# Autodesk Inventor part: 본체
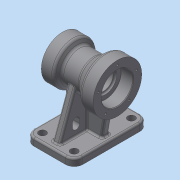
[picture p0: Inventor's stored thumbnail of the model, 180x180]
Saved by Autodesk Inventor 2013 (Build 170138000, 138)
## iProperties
Created: 2015-08
Part Number: 본체
Material: 일반
Document SubType Name: Modeling
Designer: Administrator
Density: 1 g/cm^3
Author: Administrator
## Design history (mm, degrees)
sketch "스케치1"
  geometry: L1 (0, 0)-(90, 0); L2 (0, 0)-(0, 35); L3 (0, 35)-(20, 35); L4 (20, 35)-(25.196, 26); L5 (25.196, 26)-(53.315, 26); L6 (53.315, 26)-(70, 40); L7 (70, 40)-(90, 40); L8 (90, 40)-(90, 0)
  constraints: 16 end point, 3 parallel, 2 perpendicular, 1 horizontal
  dimensions: "d0" = 90 distance of L1.start L1.end; "d1" = 70 diameter of L3 L1; "d2" = 20 distance of L2.end L3.end; "d3" = 60 deg angle of L5 L4; "d4" = 20 distance of L6.end L7.end; "d5" = 80 diameter of L7 L1; "d6" = 40 deg angle of L5 L6; "d7" = 52 diameter of L5 L1
revolve "회전1" sketch "스케치1" stored, may be unused: angle "d8" = 90 deg
sketch "스케치2"
  geometry: L1 (-61, -78)-(61, -78); L2 (61, -78)-(61, -90); L3 (61, -90)-(-61, -90); L4 (-61, -90)-(-61, -78); 2 further points
  constraints: 8 end point, 2 parallel, 1 horizontal, 1 midpoint, 1 perpendicular, 1 vertical alignment
  dimensions: "d9" = 90 distance from line of L3 point (0, 0); "d10" = 12 distance of L3.end L1.start; "d11" = 122 distance of L2.end L3.end
extrude "돌출1" join sketch "스케치2" distance "d12" = 80; taper "d13" = 0 deg
node "작업 평면1"
sketch "스케치3"
  geometry: L1 (-6, 0)-(6, 0); L2 (6, 0)-(6, -78); L3 (6, -78)-(-6, -78); L4 (-6, -78)-(-6, 0); L5 (-61, -90)-(-61, -78) reference; L6 (-61, -78)-(61, -78) reference; L7 (61, -78)-(61, -90) reference; L8 (61, -90)-(-61, -90) reference; C1 r 26 at (0, 0) reference; 2 further points
  constraints: 8 end point, 2 coincident, 2 parallel, 1 collinear, 1 horizontal, 1 midpoint, 1 perpendicular
  dimensions: "d14" = 12 distance of L1.start L1.end
extrude "돌출2" join sketch "스케치3" distance "d16" = 30; taper "d18" = 0 deg; dims "d17" = 30, "d19" = 0
sketch "스케치4"
  geometry: L1 (0, 35)-(0, -35) reference; L2 (0, -35)-(-10, -35) reference; L3 (-10, -35)-(-10, -78) reference; L4 (-10, -78)-(0, -78) reference; L5 (0, -78)-(0, -90) reference; L6 (0, -90)-(-80, -90) reference; L7 (-80, -90)-(-80, -78) reference; L8 (-80, -78)-(-70, -78) reference; L9 (-70, -78)-(-70, -40) reference; L10 (-70, -40)-(-90, -40) reference; L11 (-90, -40)-(-90, 40) reference; L12 (-90, 40)-(-70, 40) reference; L13 (-70, 40)-(-53.315, 26) reference; L14 (-53.315, 26)-(-25.196, 26) reference; L15 (-25.196, 26)-(-20, 35) reference; L16 (-20, 35)-(0, 35) reference; L17 (-70, -78)-(-76.7, -40); 1 further point
  constraints: 2 end point, 1 point on line
  dimensions: "d20" = 80 deg angle of L17 L8
feature "리브1" sketch "스케치4" dims "d21" = 1, "d22" = 12, "d23" = 0, "d24" = 0, "d25" = 1, "d26" = 1
sketch "스케치5"
  geometry: L1 (0, -35)-(-10, -35) reference; L2 (-10, -35)-(-10, -78) reference; L3 (-10, -78)-(0, -78) reference; L4 (0, -78)-(0, -90) reference; L5 (0, -90)-(-80, -90) reference; L6 (-80, -90)-(-80, -78) reference; L7 (-80, -78)-(-70, -78) reference; L8 (-70, -78)-(-76.7, -40) reference; L9 (-76.7, -40)-(-90, -40) reference; L10 (-90, -40)-(-90, 40) reference; L11 (-90, 40)-(-70, 40) reference; L12 (-70, 40)-(-53.315, 26) reference; L13 (-53.315, 26)-(-25.196, 26) reference; L14 (-25.196, 26)-(-20, 35) reference; L15 (-20, 35)-(0, 35) reference; L16 (0, 35)-(0, -35) reference; 1 further point
  node "절단 모서리 투영3"
sketch "스케치6"
  geometry: L1 (6, -78)-(61, -78) reference; L2 (61, -78)-(61, -90) reference; L3 (61, -90)-(-61, -90) reference; L4 (-61, -90)-(-61, -78) reference; L5 (-61, -78)-(-6, -78) reference; L6 (-6, -78)-(-6, -25.298) reference; L7 (6, -25.298)-(6, -78) reference; L8 (-51, -78)-(-25.92, -9.094); A1 r 26 centre (0, 0) between (6, -25.298) and (-6, -25.298) reference; 1 further point
  constraints: 2 end point, 1 point on line
  dimensions: "d27" = 70 deg angle of L5 L8; "d28" = 10 distance from line of L8.start L4
feature "리브2" sketch "스케치6" dims "d29" = 1, "d30" = 12, "d31" = 0, "d32" = 0, "d33" = 1, "d34" = 1
fillet "모깎기1" dims "d35" = 14
hole "구멍1" diameter "d38" = 38; stored, may be unused: countersink angle "d42" = 90 deg, drill point angle "d44" = 0 deg; dims "d36" = 10, "d37" = 10, "d39" = 6, "d40" = 52, "d41" = 20, "d43" = 23
hole "구멍2" diameter "d47" = 32; stored, may be unused: countersink angle "d51" = 90 deg, drill point angle "d53" = 0 deg; dims "d45" = 10, "d46" = 10, "d48" = 6, "d49" = 40, "d50" = 17, "d52" = 23
sketch "스케치7"
  geometry: C1 r 20 at (0, 0) reference; 1 further point
  constraints: 1 horizontal alignment
  dimensions: "d54" = 27 distance of C1.centre point (27, 0)
hole "구멍3" sketch "스케치7" at (27, 0) diameter "d55" = 3.242; stored, may be unused: countersink angle "d59" = 90 deg, drill point angle "d61" = 118 deg; dims "d56" = 10, "d57" = 40, "d58" = 17, "d60" = 13
sketch "스케치8"
  geometry: C1 r 26 at (0, 0) reference; 1 further point
  constraints: 1 horizontal alignment
  dimensions: "d65" = 33 distance of C1.centre point (-33, 0)
hole "구멍4" sketch "스케치8" at (-33, 0) diameter "d66" = 3.242; stored, may be unused: countersink angle "d70" = 90 deg, drill point angle "d72" = 118 deg; dims "d67" = 10, "d68" = 40, "d69" = 17, "d71" = 13
fillet "모깎기2" dims "d76" = 5
fillet "모깎기3" dims "d77" = 3
chamfer "모따기1" distance "d78" = 1; stored, may be unused: second distance "d79" = 2, angle "d80" = 45 deg
fillet "모깎기4" dims "d81" = 0.3
sketch "스케치9"
  geometry: L1 (0, 45)-(0, 0) reference; L2 (-27, 12)-(-9, 12); L3 (-9, 12)-(-9, 24); L4 (-9, 24)-(-27, 24); L5 (-27, 24)-(-27, 12); L6 (-27, 18)-(-9, 18); L7 (-18, 12)-(-18, 24); A1 r 26 centre (-78, -6) between (-52.702, 0) and (-71.185, 19.091) reference
  constraints: 12 end point, 4 midpoint, 2 parallel, 1 horizontal, 1 perpendicular
  dimensions: "d82" = 12 distance of L4.end L2.start; "d84" = 18 distance of L2.start L2.end; "d85" = 24 vertical distance of A1.centre L6.end; "d86" = 18 distance between parallel lines of L1 L7
extrude "돌출3" cut sketch "스케치9" stored distance "d87" = 12; taper "d88" = 0 deg
fillet "모깎기5" dims "d89" = 6
sketch "스케치10"
  geometry: C1 r 6 at (14, 0); C2 r 6 at (14, 94); C3 r 6 at (66, 94); C4 r 6 at (66, 0); A1 r 14 centre (14, 94) between (14, 108) and (0, 94) reference; A2 r 14 centre (14, 0) between (0, 0) and (14, -14) reference; A3 r 14 centre (66, 0) between (66, -14) and (80, 0) reference; A4 r 14 centre (66, 94) between (80, 94) and (66, 108) reference; 1 further point
  constraints: 4 centre point, 4 coincident, 3 equal radius
  dimensions: "d90" = 12 diameter of C1
extrude "돌출4" cut sketch "스케치10" stored distance "d92" = 12; taper "d93" = 0 deg
fillet "모깎기6" dims "d94" = 3
fillet "모깎기7" dims "d95" = 3
sketch "스케치11"
  geometry: L1 (-10, -3)-(1, -3) reference; L2 (-3, 37.119)-(-3, 0) reference; 2 further points
  constraints: 1 other
  dimensions: "d96" = 24 distance from line of point (13, 21) L1; "d97" = 16 distance from line of point (13, 21) L2
feature "엠보싱1" sketch "스케치11" dims "d0" = 90, "d1" = 70, "d2" = 20, "d3" = 60 deg, "d4" = 20, "d5" = 80, "d6" = 40 deg, "d7" = 52, "d98" = 0.5, "d99" = 0
node "솔리드1"
mirror "대칭1"
pattern_circular "원형 패턴1" dims angle "d63" = 360 deg
pattern_circular "원형 패턴2" dims angle "d74" = 360 deg
mirror "대칭2"
node "절단 모서리 투영1"
node "절단 모서리 투영2"
node "절단 모서리 투영4"
